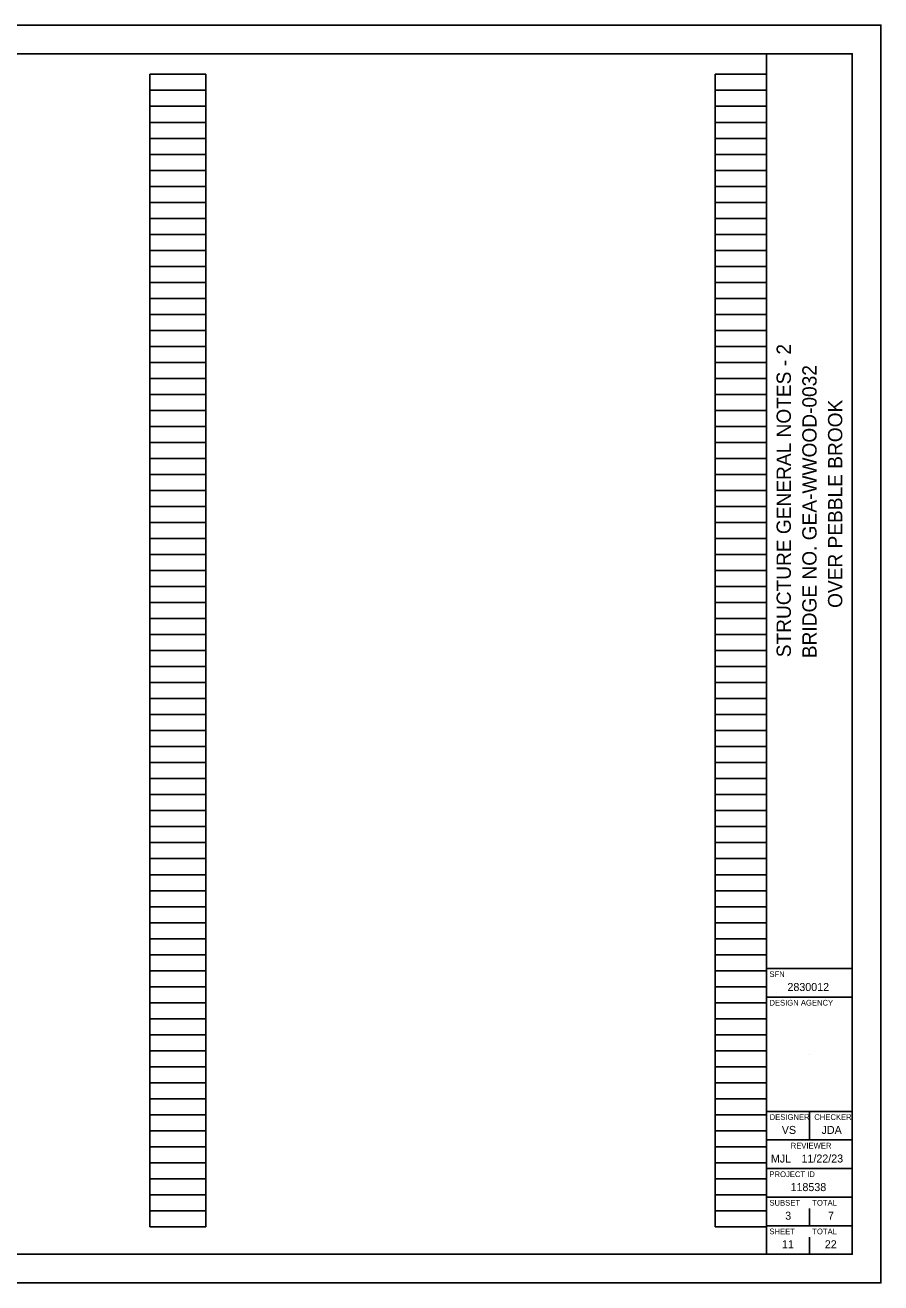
# Model space of a CAD drawing. Extents: x 0 to 34, y 0 to 22.
# Drawn here: x 19.02 to 34, y 0 to 22 of the extents above; entities that cross this region are included whole.
import ezdxf

# ---------------------------------------------------------------- set-up
doc = ezdxf.new("R2010")
doc.units = 0
for name, color, linetype in [('SH_Border', 7, 'Continuous'), ('SH_Cut_Line', 7, 'Continuous'), ('SH_Data', 7, 'Continuous')]:
    doc.layers.add(name, color=color, linetype=linetype)

msp = doc.modelspace()

# ---------------------------------------------------------------- linework, layer by layer
at = {"layer": 'SH_Border'}
for p, q in [((32, 0.5), (32, 21.5)), ((32, 5.5), (33.5, 5.5)), ((32, 5), (33.5, 5)), ((32, 3), (33.5, 3)), ((32.75, 3), (32.75, 2.5)), ((32, 2.5), (33.5, 2.5)), ((32, 2), (33.5, 2)), ((32, 1.5), (33.5, 1.5)), ((32, 1), (33.5, 1))]:
    msp.add_line(p, q, dxfattribs=at)
msp.add_lwpolyline([(1.5, 21.5), (33.5, 21.5), (33.5, 0.5), (1.5, 0.5)], close=True, dxfattribs=at)
at = {"layer": 'SH_Cut_Line'}
msp.add_lwpolyline([(0, 0), (34, 0), (34, 22), (0, 22)], close=True, dxfattribs=at)
at = {"layer": 'SH_Data'}
for p, q in [((21.207, 0.98), (21.207, 21.14)), ((21.207, 21.14), (22.187, 21.14)), ((22.187, 0.98), (22.187, 21.14)), ((31.1, 0.98), (31.1, 21.14)), ((31.1, 21.14), (32, 21.14)), ((32, 0.98), (32, 21.14)), ((21.207, 20.86), (22.187, 20.86)), ((31.1, 20.86), (32, 20.86)), ((21.207, 20.58), (22.187, 20.58)), ((31.1, 20.58), (32, 20.58)), ((21.207, 20.3), (22.187, 20.3)), ((31.1, 20.3), (32, 20.3)), ((21.207, 20.02), (22.187, 20.02)), ((31.1, 20.02), (32, 20.02)), ((21.207, 19.74), (22.187, 19.74)), ((31.1, 19.74), (32, 19.74)), ((21.207, 19.46), (22.187, 19.46)), ((31.1, 19.46), (32, 19.46)), ((21.207, 19.18), (22.187, 19.18)), ((31.1, 19.18), (32, 19.18)), ((21.207, 18.9), (22.187, 18.9)), ((31.1, 18.9), (32, 18.9)), ((21.207, 18.62), (22.187, 18.62)), ((31.1, 18.62), (32, 18.62)), ((21.207, 18.34), (22.187, 18.34)), ((31.1, 18.34), (32, 18.34)), ((21.207, 18.06), (22.187, 18.06)), ((31.1, 18.06), (32, 18.06)), ((21.207, 17.78), (22.187, 17.78)), ((31.1, 17.78), (32, 17.78)), ((21.207, 17.5), (22.187, 17.5)), ((31.1, 17.5), (32, 17.5)), ((21.207, 17.22), (22.187, 17.22)), ((31.1, 17.22), (32, 17.22)), ((21.207, 16.94), (22.187, 16.94)), ((31.1, 16.94), (32, 16.94)), ((21.207, 16.66), (22.187, 16.66)), ((31.1, 16.66), (32, 16.66)), ((21.207, 16.38), (22.187, 16.38)), ((31.1, 16.38), (32, 16.38)), ((21.207, 16.1), (22.187, 16.1)), ((31.1, 16.1), (32, 16.1)), ((21.207, 15.82), (22.187, 15.82)), ((31.1, 15.82), (32, 15.82)), ((21.207, 15.54), (22.187, 15.54)), ((31.1, 15.54), (32, 15.54)), ((21.207, 15.26), (22.187, 15.26)), ((31.1, 15.26), (32, 15.26)), ((21.207, 14.98), (22.187, 14.98)), ((31.1, 14.98), (32, 14.98)), ((21.207, 14.7), (22.187, 14.7)), ((31.1, 14.7), (32, 14.7)), ((21.207, 14.42), (22.187, 14.42)), ((31.1, 14.42), (32, 14.42)), ((21.207, 14.14), (22.187, 14.14)), ((31.1, 14.14), (32, 14.14)), ((21.207, 13.86), (22.187, 13.86)), ((31.1, 13.86), (32, 13.86)), ((21.207, 13.58), (22.187, 13.58)), ((31.1, 13.58), (32, 13.58)), ((21.207, 13.3), (22.187, 13.3)), ((31.1, 13.3), (32, 13.3)), ((21.207, 13.02), (22.187, 13.02)), ((31.1, 13.02), (32, 13.02)), ((21.207, 12.74), (22.187, 12.74)), ((31.1, 12.74), (32, 12.74)), ((21.207, 12.46), (22.187, 12.46)), ((31.1, 12.46), (32, 12.46)), ((21.207, 12.18), (22.187, 12.18)), ((31.1, 12.18), (32, 12.18)), ((21.207, 11.9), (22.187, 11.9)), ((31.1, 11.9), (32, 11.9)), ((21.207, 11.62), (22.187, 11.62)), ((31.1, 11.62), (32, 11.62)), ((21.207, 11.34), (22.187, 11.34)), ((31.1, 11.34), (32, 11.34)), ((21.207, 11.06), (22.187, 11.06)), ((31.1, 11.06), (32, 11.06)), ((21.207, 10.78), (22.187, 10.78)), ((31.1, 10.78), (32, 10.78)), ((21.207, 10.5), (22.187, 10.5)), ((31.1, 10.5), (32, 10.5)), ((21.207, 10.22), (22.187, 10.22)), ((31.1, 10.22), (32, 10.22)), ((21.207, 9.94), (22.187, 9.94)), ((31.1, 9.94), (32, 9.94)), ((21.207, 9.66), (22.187, 9.66)), ((31.1, 9.66), (32, 9.66)), ((21.207, 9.38), (22.187, 9.38)), ((31.1, 9.38), (32, 9.38)), ((21.207, 9.1), (22.187, 9.1)), ((31.1, 9.1), (32, 9.1)), ((21.207, 8.82), (22.187, 8.82)), ((31.1, 8.82), (32, 8.82)), ((21.207, 8.54), (22.187, 8.54)), ((31.1, 8.54), (32, 8.54)), ((21.207, 8.26), (22.187, 8.26)), ((31.1, 8.26), (32, 8.26)), ((21.207, 7.98), (22.187, 7.98)), ((31.1, 7.98), (32, 7.98)), ((21.207, 7.7), (22.187, 7.7)), ((31.1, 7.7), (32, 7.7)), ((21.207, 7.42), (22.187, 7.42)), ((31.1, 7.42), (32, 7.42)), ((21.207, 7.14), (22.187, 7.14)), ((31.1, 7.14), (32, 7.14)), ((21.207, 6.86), (22.187, 6.86)), ((31.1, 6.86), (32, 6.86)), ((21.207, 6.58), (22.187, 6.58)), ((31.1, 6.58), (32, 6.58)), ((21.207, 6.3), (22.187, 6.3)), ((31.1, 6.3), (32, 6.3)), ((21.207, 6.02), (22.187, 6.02)), ((31.1, 6.02), (32, 6.02)), ((21.207, 5.74), (22.187, 5.74)), ((31.1, 5.74), (32, 5.74)), ((21.207, 5.46), (22.187, 5.46)), ((31.1, 5.46), (32, 5.46)), ((21.207, 5.18), (22.187, 5.18)), ((31.1, 5.18), (32, 5.18)), ((21.207, 4.9), (22.187, 4.9)), ((31.1, 4.9), (32, 4.9)), ((21.207, 4.62), (22.187, 4.62)), ((31.1, 4.62), (32, 4.62)), ((21.207, 4.34), (22.187, 4.34)), ((31.1, 4.34), (32, 4.34)), ((21.207, 4.06), (22.187, 4.06)), ((31.1, 4.06), (32, 4.06)), ((32.75, 4), (32.75, 4)), ((21.207, 3.78), (22.187, 3.78)), ((31.1, 3.78), (32, 3.78)), ((21.207, 3.5), (22.187, 3.5)), ((31.1, 3.5), (32, 3.5)), ((21.207, 3.22), (22.187, 3.22)), ((31.1, 3.22), (32, 3.22)), ((21.207, 2.94), (22.187, 2.94)), ((31.1, 2.94), (32, 2.94)), ((21.207, 2.66), (22.187, 2.66)), ((31.1, 2.66), (32, 2.66)), ((21.207, 2.38), (22.187, 2.38)), ((31.1, 2.38), (32, 2.38)), ((21.207, 2.1), (22.187, 2.1)), ((31.1, 2.1), (32, 2.1)), ((21.207, 1.82), (22.187, 1.82)), ((31.1, 1.82), (32, 1.82)), ((21.207, 1.54), (22.187, 1.54)), ((31.1, 1.54), (32, 1.54)), ((21.207, 1.26), (22.187, 1.26)), ((31.1, 1.26), (32, 1.26)), ((32.75, 1), (32.75, 1.3)), ((21.207, 0.98), (22.187, 0.98)), ((31.1, 0.98), (32, 0.98)), ((32.375, 0.675), (32.375, 0.675)), ((32.75, 0.5), (32.75, 0.8))]:
    msp.add_line(p, q, dxfattribs=at)

# ---------------------------------------------------------------- texts
for s, p in [('STRUCTURE GENERAL NOTES - 2', (32.425, 10.943)), ('BRIDGE NO. GEA-WWOOD-0032', (32.875, 10.927)), ('OVER PEBBLE BROOK', (33.325, 11.806))]:
    msp.add_text(s, height=0.25, rotation=90, dxfattribs=at).set_placement(p)
for s, height, p in [('SFN', 0.1, (32.05, 5.35)), ('2830012', 0.14, (32.365, 5.105)), ('DESIGN AGENCY', 0.1, (32.05, 4.85)), ('DESIGNER', 0.1, (32.054, 2.85)), ('CHECKER', 0.1, (32.835, 2.85)), ('VS', 0.14, (32.266, 2.605)), ('JDA', 0.14, (32.962, 2.605)), ('REVIEWER', 0.1, (32.422, 2.35)), ('MJL', 0.14, (32.075, 2.105)), ('11/22/23', 0.14, (32.611, 2.105)), ('PROJECT ID', 0.1, (32.05, 1.85)), ('118538', 0.14, (32.419, 1.605)), ('SUBSET', 0.1, (32.05, 1.35)), ('TOTAL', 0.1, (32.8, 1.35)), ('3', 0.14, (32.326, 1.105)), ('7', 0.14, (33.074, 1.105)), ('SHEET', 0.1, (32.05, 0.85)), ('TOTAL', 0.1, (32.8, 0.85)), ('11', 0.14, (32.269, 0.605)), ('22', 0.14, (33.019, 0.605))]:
    msp.add_text(s, height=height, dxfattribs=at).set_placement(p)

doc.saveas('drawing.dxf')
